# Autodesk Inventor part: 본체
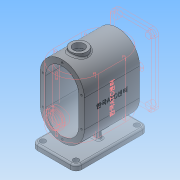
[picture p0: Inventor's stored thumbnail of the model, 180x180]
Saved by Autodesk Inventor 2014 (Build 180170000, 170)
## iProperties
Created: 2016-12
Part Number: 본체
Material: 알루미늄 6061
Document SubType Name: Modeling
Designer: mduedu
Density: 2.71 g/cm^3
Appearance: 기본값
Mass: 1146.19 g
Surface Area: 978.804 cm^2
Volume: 422.949 cm^3
Author: mduedu
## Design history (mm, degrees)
sketch "스케치1"
  geometry: L1 (40, -25)-(40, 25); L2 (-40, 25)-(-40, -25); L3 (-40, -25)-(40, 25); L4 (40, -25)-(-40, 25); L5 (0, 25)-(0, -25); A1 r 40 centre (0, 25) between (40, 25) and (-40, 25); A2 r 40 centre (0, -25) between (-40, -25) and (40, -25); 1 further point
  constraints: 10 end point, 4 point on circle, 3 tangent, 2 centre point, 2 midpoint, 2 parallel, 1 vertical
  dimensions: "d0" = 130 dimension on A2 A1; "d2" = 80 distance between parallel lines of L1 L2
extrude "돌출1" new body sketch "스케치1" stored distance "d3" = 100; taper "d4" = 0 deg
feature "쉘1" dims "d5" = 10
sketch "스케치2"
  geometry: L1 (-75, 65)-(-85, 65); L2 (-85, 65)-(-85, -65); L3 (-85, -65)-(-75, -65); L4 (-75, -65)-(-75, 65); 2 further points
  constraints: 8 end point, 2 parallel, 1 horizontal, 1 horizontal alignment, 1 midpoint, 1 perpendicular
  dimensions: "d6" = 85 distance from line of L2 point (0, 0); "d7" = 130 distance of L1.end L2.end; "d8" = 10 distance of L2.end L3.end
extrude "돌출2" join sketch "스케치2" stored distance "d9" = 80; taper "d10" = 0 deg
fillet "모깎기1" dims "d11" = 10
sketch "스케치3"
  geometry: L1 (-10, 10)-(-10, 120) reference; L2 (60, 0)-(0, 0) reference; L3 (70, 120)-(70, 10) reference; L4 (0, 130)-(60, 130) reference; A1 r 10 centre (0, 120) between (0, 130) and (-10, 120) reference; A2 r 10 centre (0, 10) between (-10, 10) and (0, 0) reference; A3 r 10 centre (60, 10) between (60, 0) and (70, 10) reference; A4 r 10 centre (60, 120) between (70, 120) and (60, 130) reference; 5 further points
  constraints: 4 coincident
hole "구멍1" sketch "스케치3" at (60, 120), (60, 10), (0, 10), (0, 120) diameter "d12" = 10; stored, may be unused: countersink angle "d16" = 90 deg, drill point angle "d18" = 118 deg; dims "d13" = 6, "d14" = 4, "d15" = 2, "d17" = 8
sketch "스케치5"
  geometry: L1 (34, 35)-(26, 35); L2 (26, 35)-(26, 95); L3 (26, 95)-(34, 95); L4 (34, 95)-(34, 35); L5 (34, 35)-(26, 95); L6 (26, 35)-(34, 95); 1 further point
  constraints: 12 end point, 2 midpoint, 2 parallel, 1 horizontal, 1 perpendicular
  dimensions: "d22" = 8 distance of L2.end L3.end; "d24" = 60 distance of L1.end L2.end
extrude "돌출3" join sketch "스케치5" stored distance "d25" = 80; taper "d26" = 0 deg
feature "면 기울기1" dims angle "d27" = 5 deg
sketch "스케치6"
  geometry: L1 (-30, -75)-(30, -75) reference; L2 (-17.524, -60.957)-(-20, -75); A1 r 40 centre (0, -25) between (-40, -25) and (40, -25) reference; 1 further point
  constraints: 2 end point, 1 point on circle, 1 point on line
  dimensions: "d28" = 20 horizontal distance of A1.centre L2.end; "d29" = 80 deg angle of L2 L1
feature "리브1" sketch "스케치6" dims "d30" = 1, "d31" = 8, "d32" = 0, "d33" = 0, "d34" = 1, "d35" = 1
fillet "모깎기2" dims "d36" = 3
fillet "모깎기3" dims "d37" = 3, "d38" = 3
node "작업 평면1"
sketch "스케치9"
  geometry: 1 further point
sketch "스케치7"
  geometry: L1 (40, 50)-(-40, 50) reference; C1 r 15 at (0, 20); 1 further point
  constraints: 1 centre point, 1 vertical alignment
  dimensions: "d40" = 30 diameter of C1; "d41" = 30 distance from line of C1.centre L1
extrude "돌출4" join sketch "스케치7" stored distance "d42" = 80; taper "d43" = 0 deg
hole "구멍2" diameter "d46" = 20; stored, may be unused: countersink angle "d50" = 90 deg, drill point angle "d52" = 118 deg; dims "d44" = 10, "d45" = 10, "d47" = 6, "d48" = 4, "d49" = 2, "d51" = 8
fillet "모깎기4" dims "d53" = 3
node "작업 평면2"
sketch "스케치8"
  geometry: C1 r 15 at (0, 0) reference; C2 r 15 at (0, 0); 1 further point
  constraints: 1 centre point, 1 coincident
  dimensions: "d55" = 30 diameter of C2
extrude "돌출5" cut sketch "스케치8" stored distance "d56" = 80; taper "d57" = 0 deg
chamfer "모따기1" distance "d58" = 1; stored, may be unused: second distance "d59" = 2, angle "d60" = 45 deg
sketch "스케치10"
  geometry: 2 further points
  constraints: 1 coincident, 1 other
feature "엠보싱1" sketch "스케치10" dims "d0" = 130, "d2" = 80, "d61" = 0.5, "d62" = 0
sketch "스케치11"
  geometry: 1 further point
hole "구멍3" sketch "스케치11" at (0, 60) diameter "d63" = 3.242; stored, may be unused: countersink angle "d67" = 90 deg, drill point angle "d69" = 120 deg; dims "d64" = 8.6, "d65" = 4, "d66" = 2, "d68" = 10.6
sketch "스케치12"
  geometry: 1 further point
hole "구멍5" sketch "스케치12" at (0, 60) diameter "d70" = 3.242; stored, may be unused: countersink angle "d74" = 90 deg, drill point angle "d76" = 120 deg; dims "d71" = 8.6, "d72" = 4, "d73" = 2, "d75" = 10.6
node "솔리드1"
mirror "대칭1"
pattern_linear "직사각형 패턴1"
pattern_linear "직사각형 패턴2"
node "투영된 루프1"
sketch "스케치13"
  geometry: L1 (-40, 25)-(-40, -25) reference; L2 (40, -25)-(40, 25) reference; L3 (35, 25)-(35, -25); L4 (-35, -25)-(-35, 25); A1 r 40 centre (0, 25) between (40, 25) and (-40, 25) reference; A2 r 40 centre (0, -25) between (-40, -25) and (40, -25) reference; A3 r 35 centre (0, 25) between (35, 25) and (-35, 25); A4 r 35 centre (0, -25) between (-35, -25) and (35, -25); 2 further points
  constraints: 5 point on circle, 4 end point, 2 centre point, 3 other
  dimensions: "d77" = 5 distance between parallel lines of L3 L2
sketch "스케치14"
  geometry: L1 (-40, 25)-(-40, -25) reference; L2 (40, -25)-(40, 25) reference; L3 (35, 25)-(35, -25); L4 (-35, -25)-(-35, 25); A1 r 40 centre (0, 25) between (40, 25) and (-40, 25) reference; A2 r 40 centre (0, -25) between (-40, -25) and (40, -25) reference; A3 r 35 centre (0, 25) between (35, 25) and (-35, 25); A4 r 35 centre (0, -25) between (-35, -25) and (35, -25); 2 further points
  constraints: 5 point on circle, 4 end point, 2 centre point, 3 other
  dimensions: "d80" = 5 distance between parallel lines of L2 L3
